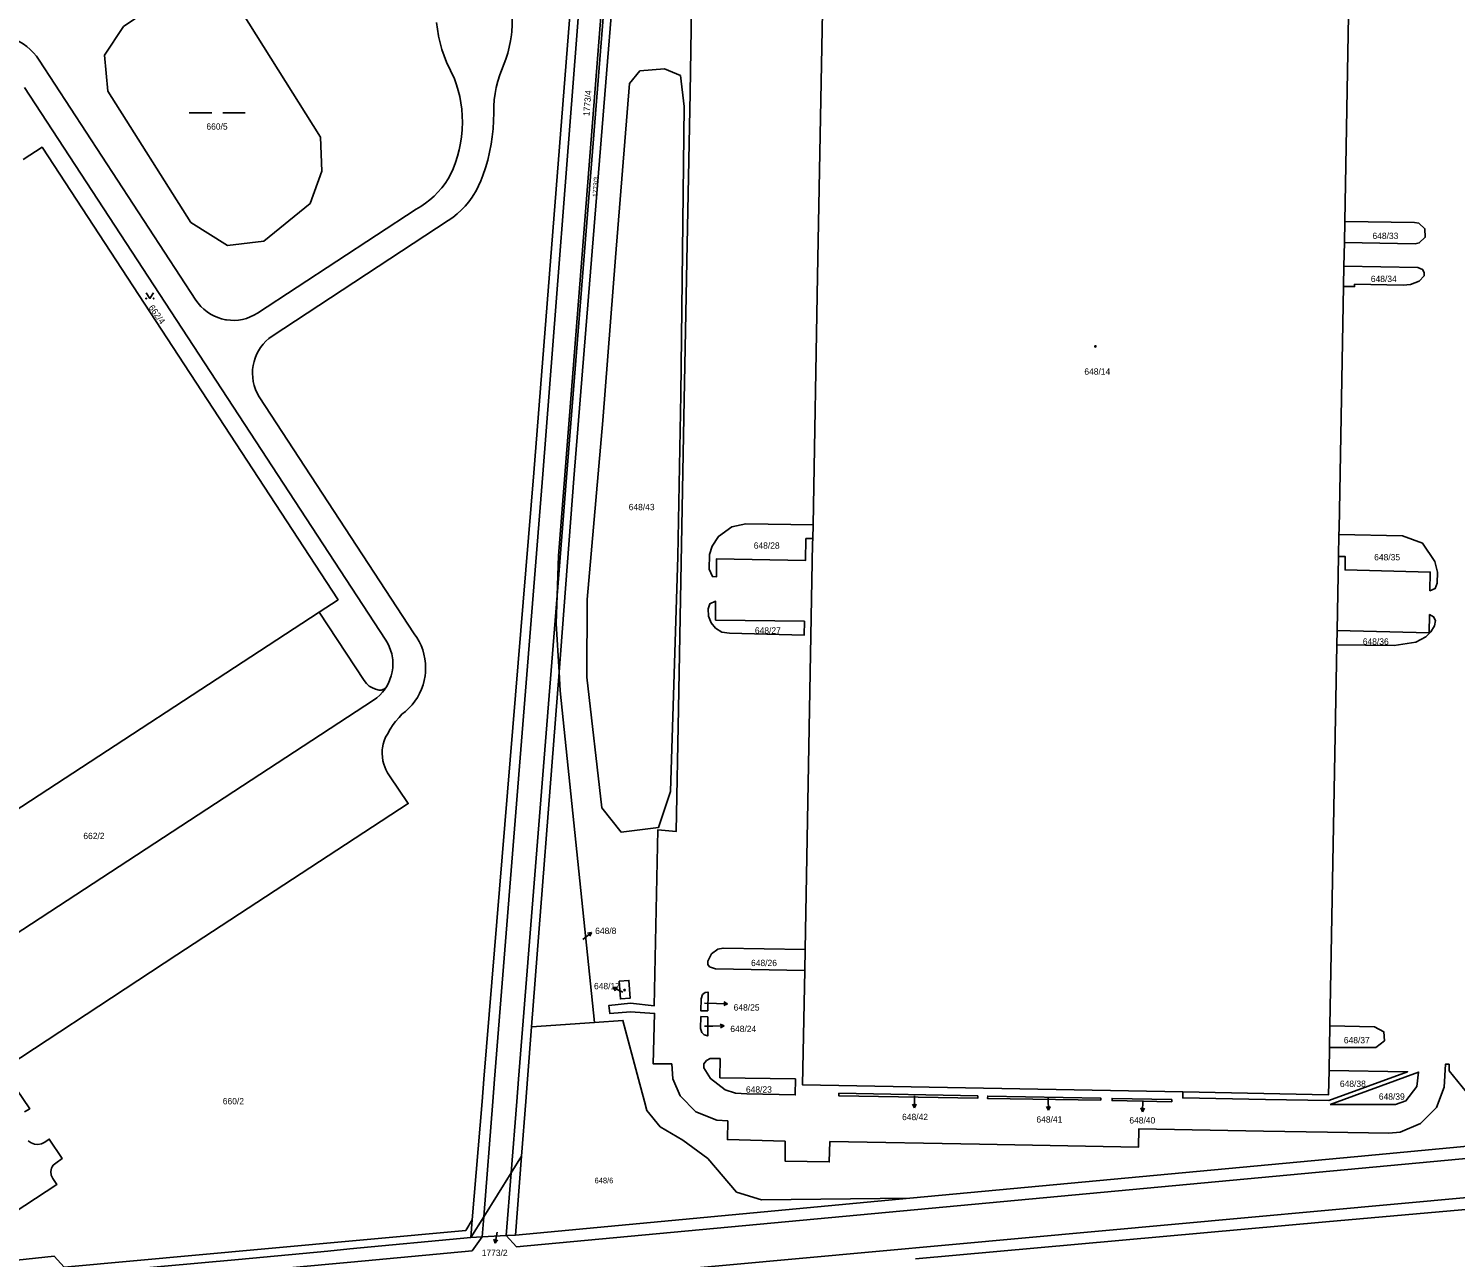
# Model space of a CAD drawing. Extents: x -724107 to -720612, y -1045267 to -1038441.
# Drawn here: x -723237.1 to -722854.2, y -1041444.7 to -1041114.7 of the extents above; entities that cross this region are included whole.
import ezdxf

# ---------------------------------------------------------------- set-up
doc = ezdxf.new("R2010")
doc.units = 0
for name, color, linetype in [('Hranice parcel', 7, 'Continuous'), ('Parcelní čísla', 7, 'Continuous'), ('Pop  PČ popisy', 7, 'Continuous'), ('Vnitřní kresba', 7, 'Continuous'), ('Značky budov', 7, 'Continuous'), ('Značky kultur', 7, 'Continuous')]:
    doc.layers.add(name, color=color, linetype=linetype)

msp = doc.modelspace()

# ---------------------------------------------------------------- linework, layer by layer
at = {"layer": 'Hranice parcel'}
for p, q in [((-722882, -1041064.26), (-722883.91, -1041166.53)), ((-723192.2, -1041187.63), (-723234.3, -1041123.21)), ((-723124.93, -1041123.76), (-723122.85, -1041128.29)), ((-723109.06, -1041123), (-723110.66, -1041127.19)), ((-723238.19, -1041130.61), (-723141.39, -1041278.72)), ((-723133.13, -1041163.23), (-723175.69, -1041191.17)), ((-723124.52, -1041166.31), (-723171.72, -1041197.3)), ((-722884.01, -1041172.22), (-722883.91, -1041166.53)), ((-722884.01, -1041172.22), (-722884.13, -1041178.53)), ((-723175.22, -1041213.62), (-723133.65, -1041277.21)), ((-723026.6, -1041247.95), (-723026.67, -1041251.65)), ((-722885.58, -1041256.48), (-722885.47, -1041250.57)), ((-722885.58, -1041256.48), (-722885.95, -1041276.36)), ((-723273.73, -1041346.35), (-723159.1, -1041271.4)), ((-722886.02, -1041280.18), (-722885.95, -1041276.36)), ((-722886.02, -1041280.18), (-722887.91, -1041382.44)), ((-723094.77, -1041287.56), (-723102.13, -1041382.75)), ((-723144.51, -1041295.05), (-723273.33, -1041379.25)), ((-723028.72, -1041361.95), (-723028.83, -1041367.61)), ((-723085.26, -1041381.56), (-723102.13, -1041382.75)), ((-722888.02, -1041388.32), (-722887.91, -1041382.44)), ((-722888.02, -1041388.32), (-722888.13, -1041394.44)), ((-723104.82, -1041417.43), (-723106.46, -1041438.67)), ((-723106.46, -1041438.67), (-723000.58, -1041428.79)), ((-723118.03, -1041434.59), (-723118.42, -1041439.33))]:
    msp.add_line(p, q, dxfattribs=at)
for points in [[(-723076.49, -1040990.35), (-723075.98, -1041005.61), (-723077.68, -1041036.16), (-723094.93, -1041256.34), (-723095.28, -1041266.92), (-723095.53, -1041274.46), (-723094.77, -1041287.56)], [(-723094.77, -1041287.56), (-723090.75, -1041235.58), (-723088.02, -1041201.14), (-723074.53, -1041033.83), (-723073.38, -1041007.35), (-723073.89, -1040989.82)], [(-723085.58, -1041026.55), (-723085.93, -1041036.15), (-723101.49, -1041234.07), (-723114.91, -1041396.8), (-723115.41, -1041402.8), (-723118.03, -1041434.59)], [(-723026.6, -1041247.95), (-723025.36, -1041181.19), (-723023.26, -1041067.61)], [(-723191.13, -1041100.27), (-723185.44, -1041101.41), (-723158.76, -1041143.88), (-723158.44, -1041153.03), (-723161.53, -1041161.72), (-723173.97, -1041171.8), (-723183.71, -1041172.98), (-723193.58, -1041166.79), (-723215.84, -1041131.56), (-723216.77, -1041121.9), (-723211.62, -1041114.22), (-723191.13, -1041100.27)], [(-723059.23, -1041109.16), (-723059.6, -1041131.98), (-723060.49, -1041177.18), (-723061.27, -1041219.21), (-723062.01, -1041258.23), (-723062.73, -1041297.4), (-723063.31, -1041330.29), (-723068.22, -1041329.86), (-723069.21, -1041377.11), (-723075.56, -1041376.38), (-723081.39, -1041377.02), (-723081.13, -1041379.14), (-723075.59, -1041378.7), (-723069.13, -1041379.15), (-723069.51, -1041392.68), (-723064.53, -1041392.71), (-723064.21, -1041396.75), (-723062.22, -1041401.27), (-723058.01, -1041405.6), (-723052.45, -1041407.77), (-723049.48, -1041408.03), (-723049.59, -1041413.03), (-723034.09, -1041413.47), (-723034.1, -1041418.79), (-723022.23, -1041419.01), (-723022.08, -1041413.54), (-722981.94, -1041414.25), (-722939.28, -1041415.06), (-722939.17, -1041410.16), (-722905.71, -1041410.73), (-722888.58, -1041411.07), (-722872.11, -1041411.33), (-722869.08, -1041411), (-722863.54, -1041408.7), (-722859.3, -1041404.44), (-722857.23, -1041398.96), (-722856.89, -1041392.79), (-722855.9, -1041392.8)], [(-723127.61, -1041113.11), (-723127.41, -1041114.92), (-723127.12, -1041116.72), (-723127.1, -1041116.81), (-723126.7, -1041118.59), (-723126.21, -1041120.35), (-723125.61, -1041122.07), (-723124.93, -1041123.76)], [(-723107.38, -1041112.16), (-723107.37, -1041113.86), (-723107.45, -1041115.56), (-723107.53, -1041116.4), (-723107.77, -1041118.08), (-723108.1, -1041119.74), (-723108.53, -1041121.39), (-723109.06, -1041123)], [(-723234.3, -1041123.21), (-723235.01, -1041122.21), (-723235.8, -1041121.27), (-723236.66, -1041120.4), (-723237.59, -1041119.6), (-723238.58, -1041118.89), (-723239.63, -1041118.25), (-723240.72, -1041117.7), (-723241.86, -1041117.24), (-723243.03, -1041116.88), (-723243.89, -1041116.68), (-723245.1, -1041116.49), (-723246.32, -1041116.39), (-723247.54, -1041116.39), (-723248.76, -1041116.5), (-723249.97, -1041116.7), (-723251.16, -1041117), (-723252.32, -1041117.4), (-723253.44, -1041117.89), (-723254.52, -1041118.46), (-723255.55, -1041119.13)], [(-723075.88, -1041129.53), (-723073.04, -1041126.11), (-723066.5, -1041125.6), (-723062.17, -1041127.37), (-723061.2, -1041135.66), (-723061.7, -1041182.4), (-723062.08, -1041213.02), (-723062.89, -1041256.45), (-723064.83, -1041319.61), (-723068.04, -1041329.21), (-723078.11, -1041330.49), (-723083.27, -1041323.99), (-723087.34, -1041288.84), (-723087.22, -1041268.04), (-723083.01, -1041220), (-723079.59, -1041176.21), (-723075.88, -1041129.53)], [(-723122.85, -1041128.29), (-723122.28, -1041129.84), (-723122.27, -1041129.85), (-723121.79, -1041131.43), (-723121.41, -1041133.04), (-723121.13, -1041134.66), (-723120.88, -1041136.43), (-723120.73, -1041138.22), (-723120.68, -1041140.01), (-723120.73, -1041141.8), (-723120.74, -1041141.99), (-723120.9, -1041143.78), (-723121.16, -1041145.55), (-723121.52, -1041147.3), (-723121.97, -1041149.04), (-723122.52, -1041150.74), (-723123.17, -1041152.41), (-723123.81, -1041153.76), (-723124.53, -1041155.06), (-723125.34, -1041156.31), (-723126.23, -1041157.51), (-723126.28, -1041157.57), (-723127.26, -1041158.7), (-723128.31, -1041159.76), (-723129.42, -1041160.75), (-723130.6, -1041161.66), (-723131.84, -1041162.49), (-723133.13, -1041163.23)], [(-723110.66, -1041127.19), (-723111.18, -1041128.85), (-723111.6, -1041130.54), (-723111.91, -1041132.18), (-723112.14, -1041133.9), (-723112.27, -1041135.63), (-723112.3, -1041137.37), (-723112.33, -1041139.54), (-723112.45, -1041141.7), (-723112.68, -1041143.85), (-723112.98, -1041145.83), (-723113.4, -1041147.95), (-723113.91, -1041150.05), (-723114.52, -1041152.13), (-723115.23, -1041154.18), (-723115.74, -1041155.6), (-723116.33, -1041156.98), (-723117.02, -1041158.32), (-723117.8, -1041159.6), (-723118.09, -1041160.05), (-723118.98, -1041161.26), (-723119.95, -1041162.41), (-723120.99, -1041163.5), (-723122.11, -1041164.51), (-723123.28, -1041165.45), (-723124.52, -1041166.31)], [(-723159.1, -1041271.4), (-723154.05, -1041268.1), (-723233.5, -1041146.6), (-723238.57, -1041149.91)], [(-722883.91, -1041166.53), (-722865.19, -1041166.84), (-722864.04, -1041167.01), (-722862.4, -1041168.48), (-722862.32, -1041170.76), (-722863.9, -1041172.29), (-722865.03, -1041172.57), (-722884.01, -1041172.22)], [(-722884.23, -1041183.97), (-722884.23, -1041183.78), (-722884.13, -1041178.53)], [(-722884.13, -1041178.53), (-722864.31, -1041178.87), (-722863.01, -1041179.45), (-722862.61, -1041180.22), (-722862.57, -1041181.11), (-722863.9, -1041182.61), (-722866.28, -1041183.46), (-722868.25, -1041183.63), (-722881.25, -1041183.42), (-722881.25, -1041184.04), (-722884.23, -1041183.97)], [(-722884.23, -1041183.97), (-722885.44, -1041249.02), (-722885.47, -1041250.57)], [(-723175.69, -1041191.17), (-723176.63, -1041191.72), (-723177.61, -1041192.19), (-723178.64, -1041192.56), (-723179.69, -1041192.84), (-723180.77, -1041193.02), (-723181.86, -1041193.1), (-723182.95, -1041193.08), (-723184.03, -1041192.96), (-723184.27, -1041192.92), (-723185.33, -1041192.68), (-723186.37, -1041192.35), (-723187.37, -1041191.92), (-723188.33, -1041191.4), (-723189.23, -1041190.8), (-723190.08, -1041190.11), (-723190.86, -1041189.35), (-723191.57, -1041188.52), (-723192.2, -1041187.63)], [(-723171.72, -1041197.3), (-723172.6, -1041197.95), (-723173.42, -1041198.69), (-723174.17, -1041199.49), (-723174.84, -1041200.36), (-723175.43, -1041201.28), (-723175.93, -1041202.26), (-723176.34, -1041203.27), (-723176.6, -1041204.12), (-723176.84, -1041205.19), (-723176.98, -1041206.28), (-723177.03, -1041207.37), (-723176.97, -1041208.47), (-723176.81, -1041209.55), (-723176.55, -1041210.62), (-723176.2, -1041211.66), (-723175.76, -1041212.66), (-723175.22, -1041213.62)], [(-723026.67, -1041251.65), (-723028.52, -1041251.68), (-723028.63, -1041257.58), (-723052.5, -1041257.1), (-723052.53, -1041261.95), (-723053.61, -1041261.89), (-723054.51, -1041259.9), (-723054.4, -1041255.91), (-723053.64, -1041253.73), (-723052, -1041251.11), (-723048.41, -1041248.53), (-723044.6, -1041247.69), (-723026.6, -1041247.95)], [(-723028.72, -1041361.95), (-723026.7, -1041253.02), (-723026.67, -1041251.65)], [(-722885.47, -1041250.57), (-722868.41, -1041250.92), (-722863, -1041252.94), (-722859.75, -1041257.87), (-722859.05, -1041260.73), (-722859.1, -1041263.67), (-722859.6, -1041265.08), (-722861.06, -1041265.69), (-722860.96, -1041260.65), (-722883.83, -1041260.11), (-722883.77, -1041256.53), (-722885.58, -1041256.48)], [(-723141.09, -1041291.48), (-723141.37, -1041291.83), (-723141.76, -1041292.12), (-723142.53, -1041292.38), (-723143.02, -1041292.34), (-723143.98, -1041292.12), (-723145.02, -1041291.68), (-723145.73, -1041291.26), (-723146.45, -1041290.6), (-723147.07, -1041289.82), (-723159.1, -1041271.4)], [(-723028.9, -1041273.88), (-723028.96, -1041277.58), (-723049.02, -1041277.1), (-723051.09, -1041276.82), (-723052.76, -1041275.77), (-723053.97, -1041274.29), (-723054.66, -1041272.48), (-723054.76, -1041270.55), (-723054.31, -1041269.19), (-723052.75, -1041268.52), (-723052.76, -1041273.57), (-723028.9, -1041273.88)], [(-722885.95, -1041276.36), (-722861.23, -1041276.95), (-722861.15, -1041272.06), (-722860.07, -1041272.65), (-722859.58, -1041273.64), (-722859.83, -1041275.07), (-722860.79, -1041276.72), (-722862.19, -1041278.07), (-722864.83, -1041279.44), (-722870.63, -1041280.4), (-722886.02, -1041280.18)], [(-723141.39, -1041278.72), (-723140.82, -1041279.64), (-723140.34, -1041280.61), (-723139.95, -1041281.62), (-723139.66, -1041282.66), (-723139.46, -1041283.73), (-723139.4, -1041284.23), (-723139.35, -1041285.31), (-723139.4, -1041286.39), (-723139.54, -1041287.46), (-723139.79, -1041288.52), (-723140.13, -1041289.54), (-723140.57, -1041290.53), (-723141.09, -1041291.48)], [(-723133.65, -1041277.21), (-723132.95, -1041278.22), (-723132.33, -1041279.29), (-723131.79, -1041280.41), (-723131.35, -1041281.56), (-723131.01, -1041282.75), (-723130.76, -1041283.96), (-723130.61, -1041285.19), (-723130.56, -1041286.42), (-723130.61, -1041287.66), (-723130.71, -1041288.53), (-723130.93, -1041289.75), (-723131.25, -1041290.94), (-723131.66, -1041292.1), (-723132.17, -1041293.23), (-723132.76, -1041294.31), (-723133.45, -1041295.34), (-723134.21, -1041296.32), (-723135.05, -1041297.22), (-723135.96, -1041298.06), (-723136.93, -1041298.82)], [(-723085.26, -1041381.56), (-723094.48, -1041292.57), (-723094.77, -1041287.56)], [(-723141.09, -1041291.48), (-723141.7, -1041292.38), (-723142.1, -1041292.87), (-723142.83, -1041293.67), (-723143.64, -1041294.4), (-723144.51, -1041295.05)], [(-723136.93, -1041298.82), (-723137.65, -1041299.68), (-723138.62, -1041300.82), (-723139.23, -1041301.61), (-723140.04, -1041302.87), (-723140.83, -1041304.16), (-723141.3, -1041305.03), (-723141.69, -1041305.94), (-723141.98, -1041306.89), (-723142.18, -1041307.86), (-723142.26, -1041308.35), (-723142.25, -1041309.33), (-723142.15, -1041310.32), (-723142.02, -1041311.3), (-723141.74, -1041312.25), (-723141.21, -1041313.64), (-723140.75, -1041314.54), (-723140.23, -1041315.38), (-723135.22, -1041322.83), (-723197.32, -1041363.4), (-723253.15, -1041400.11), (-723260.51, -1041388.79)], [(-723028.83, -1041367.61), (-723052.81, -1041367.17), (-723054.34, -1041366.63), (-723054.81, -1041366.01), (-723054.83, -1041365.14), (-723053.88, -1041363.16), (-723052.14, -1041361.9), (-723050.73, -1041361.6), (-723028.72, -1041361.95)], [(-723078.65, -1041370.48), (-723078.31, -1041375.24), (-723075.65, -1041375.05), (-723075.99, -1041370.29), (-723078.65, -1041370.48)], [(-722927.39, -1041400.24), (-723029.4, -1041398.34), (-723028.83, -1041367.61)], [(-723054.8, -1041378.5), (-723056.7, -1041378.49), (-723056.63, -1041375.19), (-723056.22, -1041374.11), (-723055.54, -1041373.54), (-723054.75, -1041373.4), (-723054.8, -1041378.5)], [(-723000.58, -1041428.79), (-723040.44, -1041429.18), (-723047.13, -1041427.14), (-723054.83, -1041418.13), (-723061.56, -1041413.15), (-723067.58, -1041409.64), (-723071.17, -1041405.24), (-723071.82, -1041402.8), (-723073.42, -1041396.8), (-723077.62, -1041381.02), (-723085.26, -1041381.56)], [(-723054.8, -1041380.06), (-723054.87, -1041385.17), (-723055.83, -1041384.92), (-723056.48, -1041384.29), (-723056.78, -1041383.19), (-723056.7, -1041380.02), (-723054.8, -1041380.06)], [(-722887.91, -1041382.44), (-722875.95, -1041382.76), (-722873.46, -1041384.07), (-722873.22, -1041386.49), (-722875.54, -1041388.3), (-722888.02, -1041388.32)], [(-722855.9, -1041392.8), (-722855.86, -1041394.56), (-722851.21, -1041400.3), (-722847.22, -1041402.71), (-722841.25, -1041403.94), (-722834.73, -1041403.65), (-722816.66, -1041401.46), (-722793.7, -1041398.75), (-722750.63, -1041393.75), (-722690.04, -1041386.79), (-722679.64, -1041385.66), (-722670.51, -1041382.99), (-722667.18, -1041382.79), (-722667.21, -1041387.63), (-722587.2, -1041378.83)], [(-723102.13, -1041382.75), (-723103.22, -1041396.8), (-723103.68, -1041402.8), (-723104.82, -1041417.43)], [(-722567.93, -1041388.13), (-722695.77, -1041400.15), (-722697.06, -1041400.4), (-722799.71, -1041409.92), (-722880.36, -1041417.57), (-723000.58, -1041428.79)], [(-723031.29, -1041396.72), (-723031.37, -1041401.04), (-723044.4, -1041400.77), (-723047.39, -1041400.52), (-723050.19, -1041399.66), (-723054.13, -1041396.64), (-723055.91, -1041393.74), (-723055.86, -1041392.68), (-723055.18, -1041391.82), (-723054.16, -1041391.23), (-723051.54, -1041391.29), (-723051.57, -1041396.43), (-723031.29, -1041396.72)], [(-722927.39, -1041400.24), (-722888.25, -1041400.97), (-722888.13, -1041394.44)], [(-722888.13, -1041394.44), (-722867.05, -1041394.83), (-722888.22, -1041402.56), (-722905.21, -1041402.26), (-722927.39, -1041401.84), (-722927.39, -1041400.24)], [(-722887.84, -1041403.62), (-722864.08, -1041394.9), (-722864.57, -1041398.76), (-722867.51, -1041402.62), (-722870.3, -1041403.62), (-722887.84, -1041403.62)], [(-723240.34, -1041399.51), (-723236.82, -1041404.74), (-723238.21, -1041405.61)], [(-722982.37, -1041401.31), (-722982.39, -1041401.91), (-723019.7, -1041401.26), (-723019.64, -1041400.59), (-722982.37, -1041401.31)], [(-722949.4, -1041402.48), (-722979.78, -1041401.96), (-722979.73, -1041401.36), (-722949.4, -1041401.87), (-722949.4, -1041402.48)], [(-722930.3, -1041402.24), (-722930.32, -1041402.85), (-722946.35, -1041402.57), (-722946.36, -1041401.95), (-722930.3, -1041402.24)], [(-723237.19, -1041413.32), (-723236.41, -1041413.9), (-723235.53, -1041414.26), (-723234.59, -1041414.32), (-723233.65, -1041414.12), (-723232.79, -1041413.73), (-723231.55, -1041412.89), (-723228.11, -1041418.11), (-723229.77, -1041419.31), (-723230.49, -1041419.91), (-723230.79, -1041420.32), (-723230.98, -1041420.73), (-723231.18, -1041421.63), (-723231.07, -1041422.59), (-723230.63, -1041423.43), (-723229.56, -1041425.09), (-723258.26, -1041443.86)], [(-722610.05, -1041410.49), (-722888.98, -1041435.1), (-722999.08, -1041445.05)], [(-723104.82, -1041417.43), (-723107.64, -1041421.97), (-723114.98, -1041433.8), (-723118.42, -1041439.33)], [(-723257.88, -1041447.24), (-723230.21, -1041444.32), (-723227.55, -1041447.27), (-723173.74, -1041442.38), (-723119.81, -1041437.42), (-723118.03, -1041434.59)], [(-723118.42, -1041439.33), (-723150.87, -1041442.38), (-723156.84, -1041442.95), (-723180.77, -1041445.2), (-723231.37, -1041449.81)], [(-723118.42, -1041439.33), (-723115.41, -1041439.16), (-723108.98, -1041438.81), (-723106.46, -1041438.67)]]:
    msp.add_lwpolyline(points, dxfattribs=at)
at = {"layer": 'Pop  PČ popisy'}
for p, q in [((-723088.39, -1041359.28), (-723086.03, -1041357.43)), ((-723086.03, -1041357.43), (-723087.12, -1041357.65)), ((-723086.03, -1041357.43), (-723086.51, -1041358.44)), ((-723080.33, -1041372.16), (-723079.21, -1041372.15)), ((-723077.63, -1041373.48), (-723080.33, -1041372.16)), ((-723080.33, -1041372.16), (-723079.65, -1041373.05)), ((-723055.71, -1041376.42), (-723052.54, -1041376.49)), ((-723052.54, -1041376.49), (-723049.54, -1041376.54)), ((-723049.54, -1041376.54), (-723050.55, -1041377.03)), ((-723049.54, -1041376.54), (-723050.53, -1041376.02)), ((-723053.47, -1041382.56), (-723050.47, -1041382.51)), ((-723050.47, -1041382.51), (-723051.48, -1041382.02)), ((-723050.47, -1041382.51), (-723051.46, -1041383.03)), ((-723055.71, -1041382.59), (-723053.47, -1041382.56)), ((-722999.39, -1041401.27), (-722999.39, -1041401.5)), ((-722999.39, -1041401.5), (-722999.39, -1041404.5)), ((-722999.39, -1041404.5), (-722999.89, -1041403.5)), ((-722999.39, -1041404.5), (-722998.89, -1041403.5)), ((-722963.37, -1041405.15), (-722963.93, -1041404.17)), ((-722963.54, -1041401.92), (-722963.53, -1041402.15)), ((-722963.53, -1041402.15), (-722963.37, -1041405.15)), ((-722963.37, -1041405.15), (-722962.93, -1041404.12)), ((-722938.18, -1041405.55), (-722938.67, -1041404.54)), ((-722938.13, -1041402.55), (-722938.18, -1041405.55)), ((-722938.18, -1041405.55), (-722937.66, -1041404.56)), ((-723111.91, -1041440.84), (-723112.23, -1041439.76)), ((-723111.39, -1041437.88), (-723111.91, -1041440.84)), ((-723111.91, -1041440.84), (-723111.24, -1041439.94))]:
    msp.add_line(p, q, dxfattribs=at)
at = {"layer": 'Vnitřní kresba'}
for p, q in [((-723099.11, -1041234.4), (-723083.66, -1041035.69)), ((-723076.76, -1041034.28), (-723092.76, -1041235.3)), ((-723092.76, -1041235.3), (-723095.28, -1041266.92)), ((-722550.33, -1041390.08), (-723106.18, -1041441.84)), ((-723107.64, -1041421.97), (-723108.98, -1041438.81)), ((-723115.41, -1041439.16), (-723114.98, -1041433.8)), ((-723118.1, -1041442.89), (-723115.41, -1041439.16)), ((-723108.98, -1041438.81), (-723106.18, -1041441.84))]:
    msp.add_line(p, q, dxfattribs=at)
for points in [[(-723114.98, -1041433.8), (-723112.51, -1041402.8), (-723112.04, -1041396.8), (-723099.11, -1041234.4)], [(-723095.28, -1041266.92), (-723105.63, -1041396.8), (-723106.11, -1041402.8), (-723107.64, -1041421.97)], [(-723234.53, -1041463.61), (-723155.83, -1041456.42), (-723149.85, -1041455.87), (-722550.28, -1041401.09)], [(-724063.89, -1041530.51), (-723156.58, -1041446.45), (-723150.6, -1041445.9), (-723118.1, -1041442.89)]]:
    msp.add_lwpolyline(points, dxfattribs=at)
at = {"layer": 'Značky budov'}
for centre in [(-722950.81, -1041200.1), (-723077.17, -1041372.89)]:
    msp.add_circle(centre, 0.175, dxfattribs=at)
at = {"layer": 'Značky kultur'}
for p, q in [((-723193.98, -1041137.39), (-723187.98, -1041137.39)), ((-723184.98, -1041137.39), (-723178.98, -1041137.39))]:
    msp.add_line(p, q, dxfattribs=at)
msp.add_lwpolyline([(-723205.55, -1041185.72), (-723204.55, -1041187.22), (-723203.55, -1041185.72)], dxfattribs=at)
for centre in [(-723205.55, -1041187.22), (-723203.55, -1041187.22)]:
    msp.add_circle(centre, 0.1, dxfattribs=at)

# ---------------------------------------------------------------- texts
at = {"layer": 'Parcelní čísla'}
for s, height, rotation, p in [('1773/4', 1.7, 85, (-723086.62, -1041138.34)), ('1773/3', 1.274, 86, (-723084.51, -1041160.01)), ('662/4', 1.7, 306, (-723205.01, -1041189.69))]:
    msp.add_text(s, height=height, rotation=rotation, dxfattribs=at).set_placement(p)
for s, height, p in [('660/5', 1.7, (-723189.39, -1041141.91)), ('648/33', 1.7, (-722876.47, -1041171.26)), ('648/34', 1.7, (-722876.91, -1041182.81)), ('648/14', 1.7, (-722953.79, -1041207.69)), ('648/43', 1.7, (-723076.07, -1041244.06)), ('648/28', 1.7, (-723042.51, -1041254.4)), ('648/35', 1.7, (-722876.01, -1041257.53)), ('648/27', 1.7, (-723042.2, -1041277.19)), ('648/36', 1.7, (-722879.07, -1041280.17)), ('662/2', 1.7, (-723222.42, -1041332.35)), ('648/8', 1.7, (-723085.06, -1041357.83)), ('648/26', 1.7, (-723043.23, -1041366.45)), ('648/17', 1.7, (-723085.38, -1041372.66)), ('648/25', 1.7, (-723047.9, -1041378.38)), ('648/24', 1.7, (-723048.8, -1041384.15)), ('648/37', 1.7, (-722884.15, -1041387.18)), ('648/38', 1.7, (-722885.21, -1041398.88)), ('648/23', 1.7, (-723044.6, -1041400.42)), ('648/39', 1.7, (-722874.76, -1041402.32)), ('660/2', 1.7, (-723185, -1041403.57)), ('648/42', 1.7, (-723002.7, -1041407.8)), ('648/41', 1.7, (-722966.64, -1041408.45)), ('648/40', 1.7, (-722941.71, -1041408.7)), ('648/6', 1.5, (-723085.21, -1041424.75)), ('1773/2', 1.7, (-723115.51, -1041444.26))]:
    msp.add_text(s, height=height, dxfattribs=at).set_placement(p)

doc.saveas('drawing.dxf')
